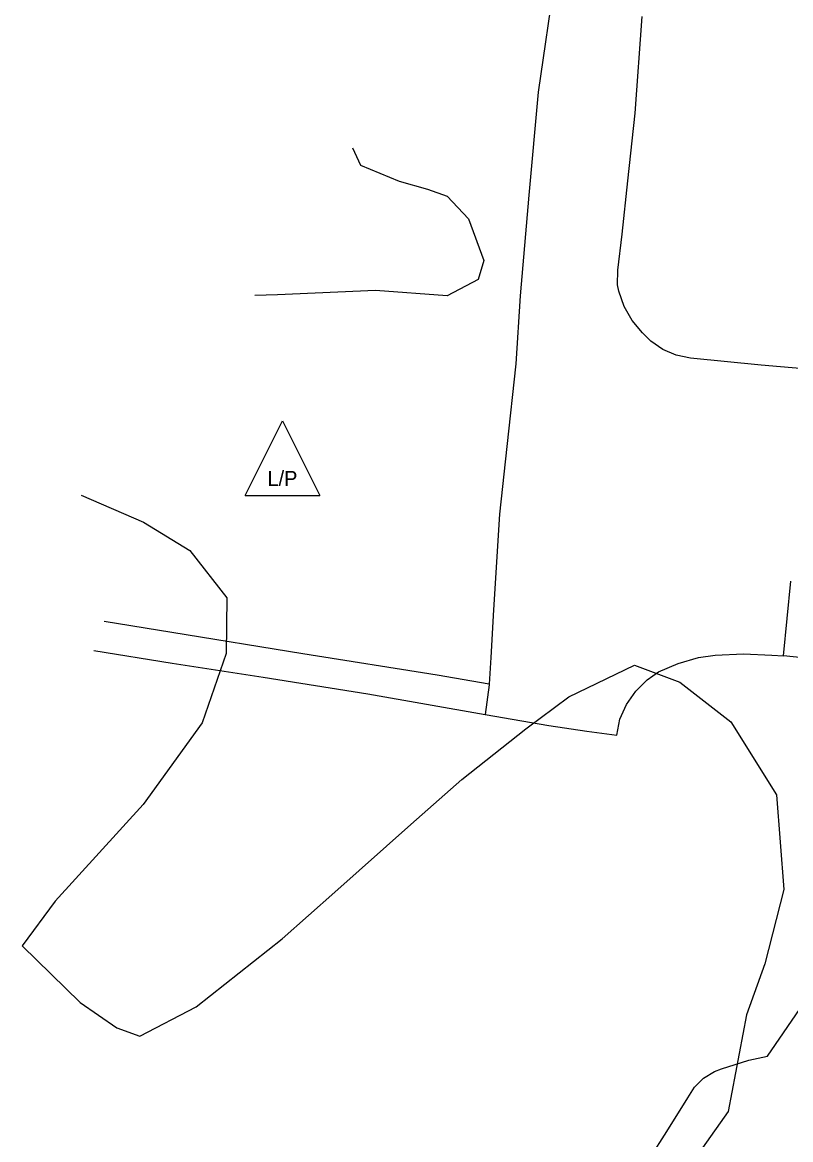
# Model space of a CAD drawing. Extents: x 2161152 to 2175754, y 602179 to 617749.
# Drawn here: x 2161984.6 to 2162087.7, y 604346.6 to 604496.4 of the extents above; entities that cross this region are included whole.
import ezdxf

# ---------------------------------------------------------------- set-up
doc = ezdxf.new("R2010")
doc.units = 0
for name, color, linetype in [('RD_EX_Conc_Sidewalk', 7, 'Continuous'), ('RD_EX_Parking_Asphalt', 7, 'Continuous'), ('RD_EX_UT', 7, 'Continuous'), ('RD_EX_VEG', 7, 'Continuous')]:
    doc.layers.add(name, color=color, linetype=linetype)

msp = doc.modelspace()

# ---------------------------------------------------------------- linework, layer by layer
at = {"layer": 'RD_EX_Conc_Sidewalk'}
for points in [[(2162047.22, 604407.71), (2162040.25, 604408.89), (2162022.23, 604411.76), (2162004.68, 604414.63), (2161995.57, 604416.1)], [(2161994.22, 604412.22), (2162004.69, 604410.51), (2162016.9, 604408.62), (2162030.93, 604406.39), (2162046.69, 604403.63)], [(2162090.57, 604411.07), (2162086.7, 604411.51)], [(2162068.76, 604344.17), (2162071.04, 604347.72), (2162073.86, 604352.23), (2162074.76, 604353.67), (2162075.97, 604354.87), (2162077.42, 604355.75), (2162078.38, 604356.11), (2162082.04, 604357.27), (2162084.55, 604357.83), (2162093.23, 604370.46)]]:
    msp.add_lwpolyline(points, dxfattribs=at)
at = {"layer": 'RD_EX_Parking_Asphalt'}
for points in [[(2162056.05, 604502.75), (2162053.79, 604487.07), (2162052.55, 604473.27), (2162051.36, 604459.74), (2162050.79, 604450.64), (2162049.6, 604439.56), (2162048.59, 604430.48), (2162047.78, 604417.66), (2162047.44, 604411.28), (2162047.22, 604407.71), (2162047.21, 604407.59), (2162046.69, 604403.63), (2162055.22, 604402.14), (2162060.3, 604401.38), (2162064.32, 604400.85), (2162064.73, 604403.01), (2162065.63, 604404.98), (2162066.87, 604406.75), (2162068.41, 604408.26), (2162069.95, 604409.33), (2162072.56, 604410.48), (2162075.3, 604411.25), (2162077.51, 604411.59), (2162081.32, 604411.77), (2162085.12, 604411.58), (2162086.7, 604411.51), (2162087.67, 604421.52)], [(2162090.47, 604449.9), (2162083.69, 604450.47), (2162074.22, 604451.39), (2162072.3, 604451.79), (2162070.5, 604452.57), (2162068.88, 604453.69), (2162067.78, 604454.79), (2162066.39, 604456.45), (2162065.31, 604458.34), (2162064.59, 604460.38), (2162064.41, 604461.24), (2162064.48, 604463.21), (2162065.06, 604468), (2162065.82, 604475.19), (2162066.8, 604484.24), (2162067.74, 604497.21)]]:
    msp.add_lwpolyline(points, dxfattribs=at)
at = {"layer": 'RD_EX_UT'}
for p, q in [((2162014.5, 604433), (2162019.5, 604443)), ((2162019.5, 604443), (2162024.5, 604433)), ((2162014.5, 604433), (2162024.5, 604433))]:
    msp.add_line(p, q, dxfattribs=at)
at = {"layer": 'RD_EX_VEG'}
for points in [[(2162028.88, 604479.61), (2162029.98, 604477.29), (2162035.15, 604475.12), (2162038.96, 604474.05), (2162041.58, 604473.12), (2162044.44, 604470.08), (2162046.51, 604464.49), (2162045.74, 604461.94), (2162041.6, 604459.76), (2162031.96, 604460.48), (2162018.85, 604459.88), (2162015.78, 604459.79)], [(2161992.52, 604433.04), (2162000.84, 604429.43), (2162007.09, 604425.61), (2162012.04, 604419.26), (2162011.96, 604411.79), (2162008.75, 604402.5), (2162000.81, 604391.57), (2161989, 604378.62), (2161984.61, 604372.64), (2161992.38, 604365.01), (2161997.3, 604361.64), (2162000.35, 604360.52), (2162007.91, 604364.46), (2162019.47, 604373.54), (2162026.5, 604379.82), (2162036.72, 604388.88), (2162043.55, 604394.9), (2162052.12, 604401.69), (2162057.9, 604406), (2162066.7, 604410.23), (2162072.79, 604407.98), (2162079.63, 604402.63), (2162085.75, 604392.88), (2162086.73, 604380.19), (2162084.2, 604370.2), (2162081.72, 604363.35), (2162079.25, 604350.41), (2162075.84, 604345.53)]]:
    msp.add_lwpolyline(points, dxfattribs=at)

# ---------------------------------------------------------------- texts
at = {"layer": 'RD_EX_UT'}
msp.add_text('L/P', height=2, dxfattribs=at).set_placement((2162017.49, 604434.28))

doc.saveas('drawing.dxf')
